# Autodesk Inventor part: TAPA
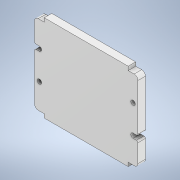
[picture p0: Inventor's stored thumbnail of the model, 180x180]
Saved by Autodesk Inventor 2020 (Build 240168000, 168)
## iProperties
Created: 2022-09
Part Number: TAPA
Material: Tuberías de PVC
Document SubType Name: Modeling
Designer: SEBAS
Density: 1.4 g/cm^3
Appearance: Suave - Blanco
Author: SEBAS
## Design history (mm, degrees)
sketch "Boceto1"
  geometry: L1 (-37, -29)-(37, -29); L2 (37, -29)-(37, 29); L3 (37, 29)-(-37, 29); L4 (-37, 29)-(-37, -29); L5 (-37, -29)-(37, 29); L6 (37, -29)-(-37, 29); L7 (-37, 0)-(0, 0); L8 (0, 0)-(0, 29); L9 (-28, 29)-(-28, 26.5); L10 (-28, 26.5)-(-32, 26.5); L11 (-32, 26.5)-(-32, 24); L12 (-32, 24)-(-34.5, 24); L13 (-34.5, 24)-(-34.5, 12); L14 (-34.5, 12)-(-33.5, 12); L15 (-33.5, 12)-(-33.5, 11); L16 (-33.5, 11)-(-31.25, 11); L17 (-31.25, 11)-(-31.25, 8); L18 (-31.25, 8)-(-33.5, 8); L19 (-33.5, 7)-(-34.5, 7); L20 (-33.5, 7)-(-33.5, 8); L21 (-34.5, 7)-(-34.5, 0); L22 (-28, 29)-(0, 29); L23 (-34.5, 0)-(-34.5, -24); L24 (-32, -24)-(-34.5, -24); L25 (-32, -24)-(-32, -26.5); L26 (0, 29)-(28, 29); L27 (28, 29)-(28, 26.5); L28 (28, 26.5)-(32, 26.5); L29 (32, 26.5)-(32, 24); L30 (32, 24)-(37, 24); L31 (34.5, 24)-(34.5, 0); L32 (34.5, 0)-(34.5, -7); L33 (33.5, -7)-(34.5, -7); L34 (33.5, -7)-(33.5, -8); L35 (33.5, -8)-(31.25, -8); L36 (31.25, -11)-(33.5, -11); L37 (31.25, -8)-(31.25, -11); L38 (32, -24)-(34.5, -24); L39 (32, -24)-(32, -26.5); L40 (34.5, -24)-(34.5, -12); L41 (-32, -26.5)-(-28, -26.5); L42 (-28, -26.5)-(-28, -29); L43 (-28, -29)-(0, -29); L44 (32, -26.5)-(28, -26.5); L45 (28, -26.5)-(28, -29); L46 (28, -29)-(0, -29); C1 r 1.5 at (-31.25, -9.5); C2 r 1.5 at (31.25, 9.5); A1 r 2.5 centre (-32, 24) between (-32, 26.5) and (-34.5, 24); A2 r 1 centre (-33.5, 12) between (-34.5, 12) and (-33.5, 11); A3 r 1.5 centre (-31.25, 9.5) between (-31.25, 8) and (-31.25, 11); A4 r 1 centre (-33.5, 7) between (-33.5, 8) and (-34.5, 7); A5 r 2.5 centre (-32, -24) between (-34.5, -24) and (-32, -26.5); A6 r 2.5 centre (32, 24) between (34.5, 24) and (32, 26.5); A7 r 1 centre (33.5, -7) between (33.5, -8) and (34.5, -7); A8 r 1.5 centre (31.25, -9.5) between (31.25, -8) and (31.25, -11); A9 r 1 centre (33.5, -12) between (34.5, -12) and (33.5, -11); A10 r 2.5 centre (32, -24) between (32, -26.5) and (34.5, -24); 5 further points
  constraints: 92 end point, 21 point on circle, 13 horizontal, 13 perpendicular, 12 centre point, 11 equal length, 11 vertical alignment, 10 vertical, 9 equal radius, 9 midpoint, 8 horizontal alignment, 7 point on line, 7 tangent, 2 collinear, 2 parallel
  dimensions: "d0" = 58 distance between parallel lines of L1 L3; "d1" = 74 distance of L2.end L3.end; "d17" = 2.5 distance of L9.start L9.end; "d18" = 4 distance of L9.end L10.end; "d20" = 2.5 radius of A1; "d21" = 12 distance of L12.end L13.end; "d22" = 2.5 distance between parallel lines of L4 L13; "d23" = 2 diameter of A2; "d24" = 2.25 distance of L15.end L16.end; "d26" = 2.5 distance between parallel lines of L2 L31; "d30" = 3 distance between parallel lines of L16 L18
extrude "Extrusión1" new body sketch "Boceto1" distance "d15" = 5; taper "d16" = 0 deg
node "Sólido1"
